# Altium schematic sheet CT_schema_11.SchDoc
size 274 x 160 mm
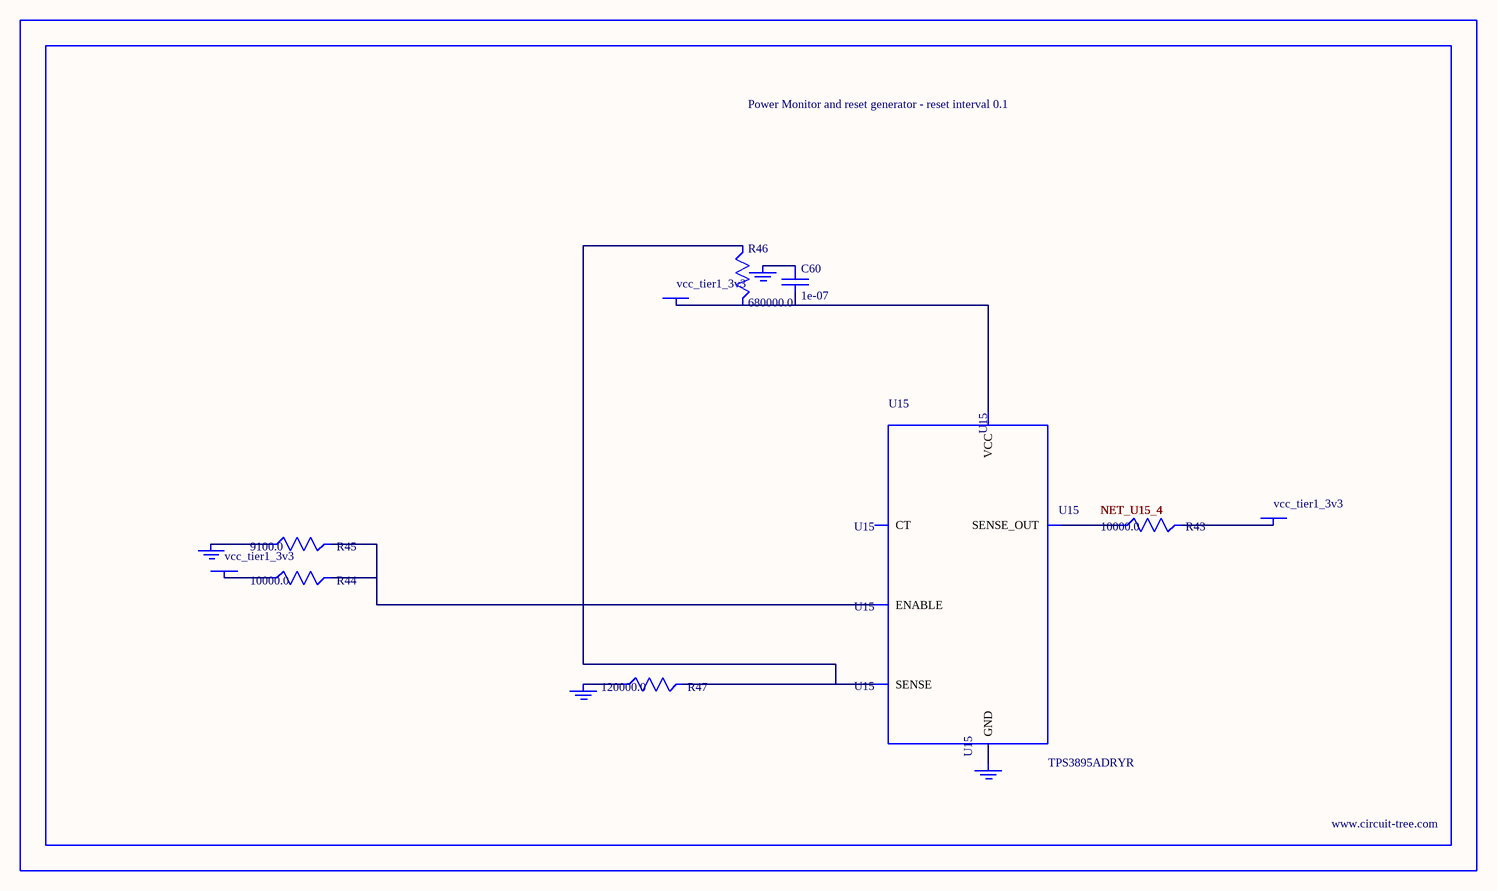
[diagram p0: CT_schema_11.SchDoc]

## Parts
BORDER10  (no value)
C60  1e-07  [C0402]
GND_INSTANCE_10_0  (no value)
GND_INSTANCE_10_1  (no value)
GND_INSTANCE_10_2  (no value)
GND_INSTANCE_10_3  (no value)
POWER_INSTANCE_10_0  vcc_tier1_3v3
POWER_INSTANCE_10_1  vcc_tier1_3v3
POWER_INSTANCE_10_2  vcc_tier1_3v3
R43  10000.0  [R0603]
R44  10000.0  [R0603]
R45  9100.0  [R0603]
R46  680000.0  [R0603]
R47  120000.0  [R0603]
U15  TPS3895ADRYR  [SON-6]

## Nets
NetC60_1: C60.1 GND_INSTANCE_10_2.0(GND)
NetC60_2: C60.2 POWER_INSTANCE_10_2.0(PWR) R46.2 U15.6(VCC)
NetGND_INSTANCE_10_0_0: GND_INSTANCE_10_0.0(GND) R45.1
NetGND_INSTANCE_10_1_0: GND_INSTANCE_10_1.0(GND) R47.1
NetGND_INSTANCE_10_3_0: GND_INSTANCE_10_3.0(GND) U15.2(GND)
NetPOWER_INSTANCE_10_0_0: POWER_INSTANCE_10_0.0(PWR) R44.1
NetPOWER_INSTANCE_10_1_0: POWER_INSTANCE_10_1.0(PWR) R43.2
NetR43_1: R43.1 U15.4(SENSE_OUT)
NetR44_2: R44.2 R45.2 U15.1(ENABLE)
NetR46_1: R46.1 R47.2 U15.3(SENSE)

Not connected (* = marked no-connect by the designer): U15 5(CT)

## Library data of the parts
BORDER10 = BORDER_PAGE10
C60 = C0402C104K3RACTU
GND_INSTANCE_10_0-GND_INSTANCE_10_3 = GND
POWER_INSTANCE_10_0-POWER_INSTANCE_10_2 = PWR
R43 R44 = RC0603JR-0710KL
R45 = RC0603JR-079K1L
R46 = RC0603JR-07680KL
R47 = RC0603JR-07120KL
